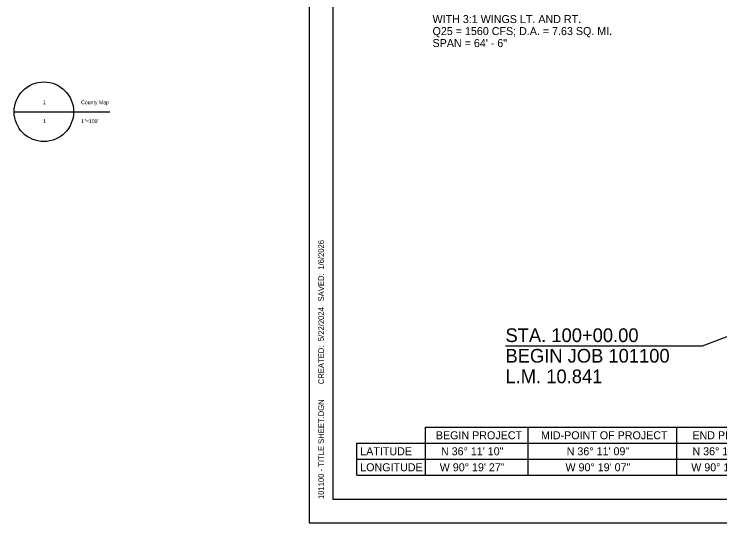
# Model space of a CAD drawing. Extents: x -0.3 to 2.65, y 0 to 1.9.
# Drawn here: x -0.258 to 0.359, y 0 to 0.445 of the extents above; entities that cross this region are included whole.
import ezdxf

# ---------------------------------------------------------------- set-up
doc = ezdxf.new("R2010")
doc.units = 0
for name, color, linetype in [('Default', 7, 'Continuous'), ('SHET_Annotations', 7, 'Continuous'), ('SHET_Border-Lines', 7, 'Continuous'), ('SHET_Border-Text', 7, 'Continuous')]:
    doc.layers.add(name, color=color, linetype=linetype)

msp = doc.modelspace()

# ---------------------------------------------------------------- linework, layer by layer
at = {"layer": 'Default'}
for p, q in [((-0.25813, 0.35978), (-0.20605, 0.35978)), ((-0.23187, 0.35978), (-0.17454, 0.35978)), ((0.34423, 0.15508), (0.45189, 0.196)), ((0.17173, 0.15508), (0.34423, 0.15508))]:
    msp.add_line(p, q, dxfattribs=at)
msp.add_circle((-0.23209, 0.35978), 0.02604, dxfattribs=at)
at = {"layer": 'SHET_Border-Lines'}
for points in [[(0, 0), (1.41667, 0), (1.41667, 0.91667), (0, 0.91667)], [(0.02083, 0.02083), (1.39583, 0.02083), (1.39583, 0.89583), (0.02083, 0.89583)]]:
    msp.add_lwpolyline(points, close=True, dxfattribs=at)
at = {"layer": 'SHET_Border-Text'}
for p, q in [((0.10167, 0.04167), (0.10167, 0.08367)), ((0.10167, 0.08367), (0.41167, 0.08367)), ((0.19167, 0.04167), (0.19167, 0.08367)), ((0.32167, 0.04167), (0.32167, 0.08367)), ((0.04167, 0.04167), (0.04167, 0.06967)), ((0.04167, 0.06967), (0.41167, 0.06967)), ((0.04167, 0.05567), (0.41167, 0.05567)), ((0.04167, 0.04167), (0.41167, 0.04167))]:
    msp.add_line(p, q, dxfattribs=at)

# ---------------------------------------------------------------- texts
at = {"layer": 'Default'}
for s, height, p in [('1', 0.00328, (-0.23294, 0.36635)), ('County Map', 0.003281, (-0.19954, 0.36635)), ('1', 0.00328, (-0.23272, 0.34994)), ('1"=100\'', 0.003281, (-0.19954, 0.34994)), ('STA. 100+00.00', 0.012, (0.17173, 0.15824)), ('BEGIN JOB 101100', 0.012, (0.17173, 0.14024)), ('L.M. 10.841', 0.012, (0.17173, 0.12224))]:
    msp.add_text(s, height=height, dxfattribs=at).set_placement(p)
at = {"layer": 'SHET_Annotations'}
for s, p in [('WITH 3:1 WINGS LT. AND RT.', (0.10792, 0.43738)), ('Q25 = 1560 CFS; D.A. = 7.63 SQ. MI.', (0.10792, 0.42688)), ('SPAN = 64\' - 6"', (0.10792, 0.41638)), ('N 36° 11\' 10"', (0.11529, 0.05917)), ('N 36° 11\' 09"', (0.22529, 0.05917)), ('N 36° 11\' 09"', (0.33529, 0.05917)), ('W 90° 19\' 27"', (0.11423, 0.04517)), ('W 90° 19\' 07"', (0.22423, 0.04517)), ('W 90° 18\' 51"', (0.33423, 0.04517))]:
    msp.add_text(s, height=0.007, dxfattribs=at).set_placement(p)
at = {"layer": 'SHET_Border-Text'}
for s, p in [('1/6/2026', (0.01292, 0.22154)), ('1/6/2026', (0.01292, 0.22154)), ('  SAVED: ', (0.01292, 0.19009)), ('  SAVED: ', (0.01292, 0.19009)), ('5/22/2024', (0.01292, 0.15903)), ('5/22/2024', (0.01292, 0.15903)), ('     CREATED: ', (0.01292, 0.11206)), ('     CREATED: ', (0.01292, 0.11206)), ('101100 - TITLE SHEET.DGN', (0.01292, 0.02083)), ('101100 - TITLE SHEET.DGN', (0.01292, 0.02083))]:
    msp.add_text(s, height=0.005, rotation=90, dxfattribs=at).set_placement(p)
for s, p in [('BEGIN PROJECT', (0.11082, 0.07317)), ('MID-POINT OF PROJECT', (0.20277, 0.07317)), ('END PROJECT', (0.33526, 0.07317)), ('LATITUDE', (0.04467, 0.05917)), ('LONGITUDE', (0.04467, 0.04517))]:
    msp.add_text(s, height=0.007, dxfattribs=at).set_placement(p)

doc.saveas('drawing.dxf')
